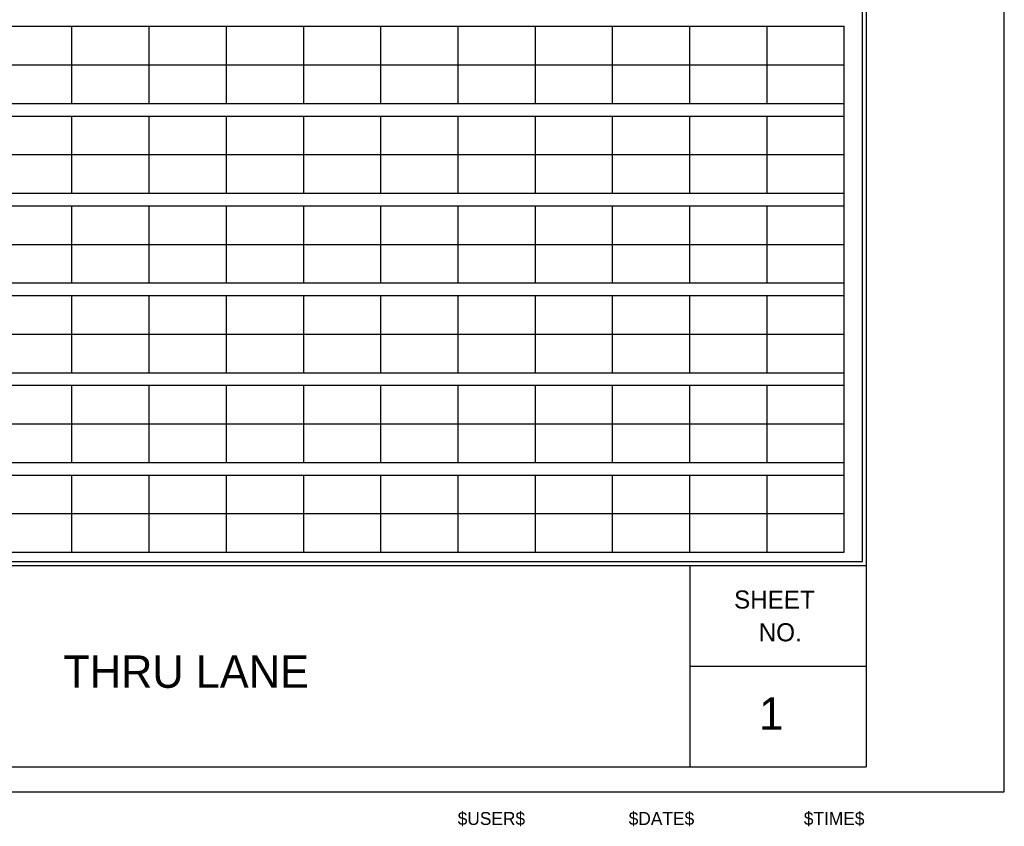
# Model space of a CAD drawing. Extents: x 119523 to 121850, y -23542 to -19972.
# Drawn here: x 121298 to 121850, y -23542 to -23090 of the extents above; entities that cross this region are included whole.
import ezdxf

# ---------------------------------------------------------------- set-up
doc = ezdxf.new("R2010")
doc.units = 0
for name, color, linetype in [('PlotBorder_dp', 7, 'Continuous'), ('SheetBorder_dp', 7, 'Continuous'), ('SheetLines_dp', 7, 'Continuous'), ('SheetLinesMisc2_dp', 7, 'Continuous'), ('TextMisc', 7, 'Continuous')]:
    doc.layers.add(name, color=color, linetype=linetype)

msp = doc.modelspace()

# ---------------------------------------------------------------- linework, layer by layer
at = {"layer": 'PlotBorder_dp'}
msp.add_lwpolyline([(119522.87, -23522.86), (121850.2, -23522.86), (121850.2, -22027.72), (119522.87, -22027.72)], close=True, dxfattribs=at)
at = {"layer": 'SheetBorder_dp'}
for p, q in [((121772.62, -22041.83), (121772.62, -23508.75)), ((119600.45, -23395.91), (121772.62, -23395.91)), ((119600.45, -23508.75), (121772.62, -23508.75))]:
    msp.add_line(p, q, dxfattribs=at)
at = {"layer": 'SheetLines_dp'}
for p, q in [((121673.89, -23508.75), (121673.89, -23395.91)), ((121673.89, -23452.33), (121772.62, -23452.33))]:
    msp.add_line(p, q, dxfattribs=at)
at = {"layer": 'SheetLinesMisc2_dp'}
for p, q in [((121770.65, -23393.69), (121770.65, -22045.18)), ((120694.9, -23093.43), (121760.29, -23093.43)), ((121326.9, -23093.43), (121326.9, -23136.72)), ((121370.23, -23093.43), (121370.23, -23136.72)), ((121413.57, -23093.43), (121413.57, -23136.72)), ((121456.92, -23093.43), (121456.92, -23136.72)), ((121500.26, -23093.43), (121500.26, -23136.72)), ((121543.59, -23093.43), (121543.59, -23136.72)), ((121586.93, -23093.43), (121586.93, -23136.72)), ((121630.28, -23093.43), (121630.28, -23136.72)), ((121673.62, -23093.43), (121673.62, -23136.72)), ((121716.96, -23093.43), (121716.96, -23136.72)), ((121760.29, -23388.43), (121760.29, -23093.43)), ((120694.9, -23115.06), (121760.29, -23115.06)), ((120694.9, -23136.72), (121760.29, -23136.72)), ((120694.9, -23143.78), (121760.29, -23143.78)), ((121326.9, -23143.78), (121326.9, -23187.06)), ((121370.23, -23143.78), (121370.23, -23187.06)), ((121413.57, -23143.78), (121413.57, -23187.06)), ((121456.92, -23143.78), (121456.92, -23187.06)), ((121500.26, -23143.78), (121500.26, -23187.06)), ((121543.59, -23143.78), (121543.59, -23187.06)), ((121586.93, -23143.78), (121586.93, -23187.06)), ((121630.28, -23143.78), (121630.28, -23187.06)), ((121673.62, -23143.78), (121673.62, -23187.06)), ((121716.96, -23143.78), (121716.96, -23187.06)), ((120694.9, -23165.42), (121760.29, -23165.42)), ((120694.9, -23187.06), (121760.29, -23187.06)), ((120694.9, -23194.12), (121760.29, -23194.12)), ((121326.9, -23194.12), (121326.9, -23237.41)), ((121370.23, -23194.12), (121370.23, -23237.41)), ((121413.57, -23194.12), (121413.57, -23237.41)), ((121456.92, -23194.12), (121456.92, -23237.41)), ((121500.26, -23194.12), (121500.26, -23237.41)), ((121543.59, -23194.12), (121543.59, -23237.41)), ((121586.93, -23194.12), (121586.93, -23237.41)), ((121630.28, -23194.12), (121630.28, -23237.41)), ((121673.62, -23194.12), (121673.62, -23237.41)), ((121716.96, -23194.12), (121716.96, -23237.41)), ((120694.9, -23215.76), (121760.29, -23215.76)), ((120694.9, -23237.41), (121760.29, -23237.41)), ((120694.9, -23244.46), (121760.29, -23244.46)), ((121326.9, -23244.46), (121326.9, -23287.75)), ((121370.23, -23244.46), (121370.23, -23287.75)), ((121413.57, -23244.46), (121413.57, -23287.75)), ((121456.92, -23244.46), (121456.92, -23287.75)), ((121500.26, -23244.46), (121500.26, -23287.75)), ((121543.59, -23244.46), (121543.59, -23287.75)), ((121586.93, -23244.46), (121586.93, -23287.75)), ((121630.28, -23244.46), (121630.28, -23287.75)), ((121673.62, -23244.46), (121673.62, -23287.75)), ((121716.96, -23244.46), (121716.96, -23287.75)), ((120694.9, -23266.09), (121760.29, -23266.09)), ((120694.9, -23287.75), (121760.29, -23287.75)), ((120694.9, -23294.81), (121760.29, -23294.81)), ((121326.9, -23294.81), (121326.9, -23338.09)), ((121370.23, -23294.81), (121370.23, -23338.09)), ((121413.57, -23294.81), (121413.57, -23338.09)), ((121456.92, -23294.81), (121456.92, -23338.09)), ((121500.26, -23294.81), (121500.26, -23338.09)), ((121543.59, -23294.81), (121543.59, -23338.09)), ((121586.93, -23294.81), (121586.93, -23338.09)), ((121630.28, -23294.81), (121630.28, -23338.09)), ((121673.62, -23294.81), (121673.62, -23338.09)), ((121716.96, -23294.81), (121716.96, -23338.09)), ((120694.9, -23316.46), (121760.29, -23316.46)), ((120694.9, -23338.09), (121760.29, -23338.09)), ((120694.9, -23345.15), (121760.29, -23345.15)), ((121326.9, -23345.15), (121326.9, -23388.43)), ((121370.23, -23345.15), (121370.23, -23388.43)), ((121413.57, -23345.15), (121413.57, -23388.43)), ((121456.92, -23345.15), (121456.92, -23388.43)), ((121500.26, -23345.15), (121500.26, -23388.43)), ((121543.59, -23345.15), (121543.59, -23388.43)), ((121586.93, -23345.15), (121586.93, -23388.43)), ((121630.28, -23345.15), (121630.28, -23388.43)), ((121673.62, -23345.15), (121673.62, -23388.43)), ((121716.96, -23345.15), (121716.96, -23388.43)), ((120694.9, -23366.79), (121760.29, -23366.79)), ((120694.9, -23388.43), (121760.29, -23388.43)), ((119604.34, -23393.68), (121770.65, -23393.68))]:
    msp.add_line(p, q, dxfattribs=at)

# ---------------------------------------------------------------- texts
at = {"layer": 'TextMisc'}
for s, p in [('SHEET', (121698.57, -23420.03)), ('NO.', (121712.39, -23438.37))]:
    msp.add_text(s, height=10.156, rotation=359.8607, dxfattribs=at).set_placement(p)
for s, height, p in [('THRU LANE', 18.182, (121322.27, -23464.47)), ('1', 18.18, (121712.68, -23488.03)), ('$USER$', 7.273, (121543.5, -23541.42)), ('$DATE$', 7.273, (121639.46, -23541.42)), ('$TIME$', 7.273, (121737.69, -23541.42))]:
    msp.add_text(s, height=height, dxfattribs=at).set_placement(p)

doc.saveas('drawing.dxf')
